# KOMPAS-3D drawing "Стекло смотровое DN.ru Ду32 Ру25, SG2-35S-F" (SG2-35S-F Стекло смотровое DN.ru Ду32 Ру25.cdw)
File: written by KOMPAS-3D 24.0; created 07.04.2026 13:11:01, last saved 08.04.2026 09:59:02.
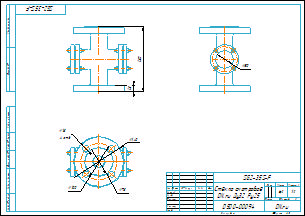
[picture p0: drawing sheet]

Document properties: Автор: Main; Форматы листов документа: A3; Полное имя файла: SG2-35S-F Стекло смотровое DN.ru Ду32 Ру25.m3d; Масса: 6.2; Наименование: Стекло смотровое DN.ru Ду32 Ру25; Количество листов документа: 1; Примечание: D500-00094

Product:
- Body: Тело 1  | qty 1
    Масса: 6.03947
- Part/product: Стекло смотровое DN.ru Ду32 Ру25  | designation SG2-35S-F
    Масса: 6.2
    Раздел спецификации: Прочие изделия
    Примечание: D500-00094

Views: Вид 1, Снизу, Проекционный вид 2
Referenced files in D:\DN.ru Аутсерс\Стекло смотровое DN.ru\Стекло смотровое DN.ru SG2-34G-F тип В ГОСТ 21836-2021 Ду100 Ру16, углеродистая сталь, фланцевое\: SG2-34G-F тип В Стекло смотровое DN.ru Ду100 Ру16.m3d, SG2-34G-F тип ВСтекло смотровое DN.ru Ду100 Ру16.cdw
Referenced files in D:\DN.ru Аутсерс\Стекло смотровое DN.ru\SG2-35S-F Стекло смотровое DN.ru Ду32 Ру25\: SG2-35S-F Стекло смотровое DN.ru Ду32 Ру25.m3d
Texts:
  SG2-35S-F
  Стекло смотровое
  DN.ru Ду32 Ру25
  Стекло смотровое DN.ru Ду32 Ру25
  SG2-35S-F Стекло смотровое DN.ru Ду32 Ру25
Dimensions and other numbers on the sheet: 0; 3; 2; 4; 180; 18; 4 отв.; 100; 78; 140; 1:2; 1; 6,2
